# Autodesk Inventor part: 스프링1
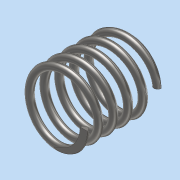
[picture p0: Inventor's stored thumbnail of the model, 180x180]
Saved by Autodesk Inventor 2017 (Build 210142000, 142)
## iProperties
Part Number: 스프링1
Material: 스테인레스 스틸
Document SubType Name: Modeling
Designer: MRC
Density: 8 g/cm^3
Appearance: 반연마
Mass: 6.57569 g
Surface Area: 16.7185 cm^2
Volume: 0.821961 cm^3
Author: MRC
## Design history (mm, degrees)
sketch "스케치1"
  geometry: L1 (0, 0)-(0, 20.5); L2 (0, 0)-(8.5, 0); L3 (0, 20.5)-(7.5, 20.5); C1 r 1 at (8.5, 0)
  constraints: 6 end point, 2 horizontal, 1 centre point, 1 coincident, 1 vertical
  dimensions: "d0" = 20.5 distance of L1.start L1.end (derived); "d1" = 2 diameter of C1; "d2" = 17 diameter of L2.end L1
feature "코일1" sketch "스케치1" pitch "d3" = 10; turns "d5" = 5; dims "d4" = 20.5 (= d0), "d6" = 0, angle "d7" = 90 deg, angle "d8" = 90 deg, "d9" = 0, "d10" = 0
sketch "스케치2"
  geometry: L1 (20.5, 18.5)-(0, 18.5); L2 (0, 18.5)-(0, -18.5); L3 (0, -18.5)-(20.5, -18.5); L4 (20.5, -18.5)-(20.5, 18.5); 2 further points
  constraints: 8 end point, 2 parallel, 1 coincident, 1 horizontal, 1 midpoint, 1 perpendicular
  dimensions: "d11" = 37 distance of L3.end L1.start; "d12" = 20.5 distance of L2.end L3.end (= d0)
extrude "돌출1" sketch "스케치2" stored distance "d13" = 0; taper "d14" = 0 deg
node "솔리드1"
